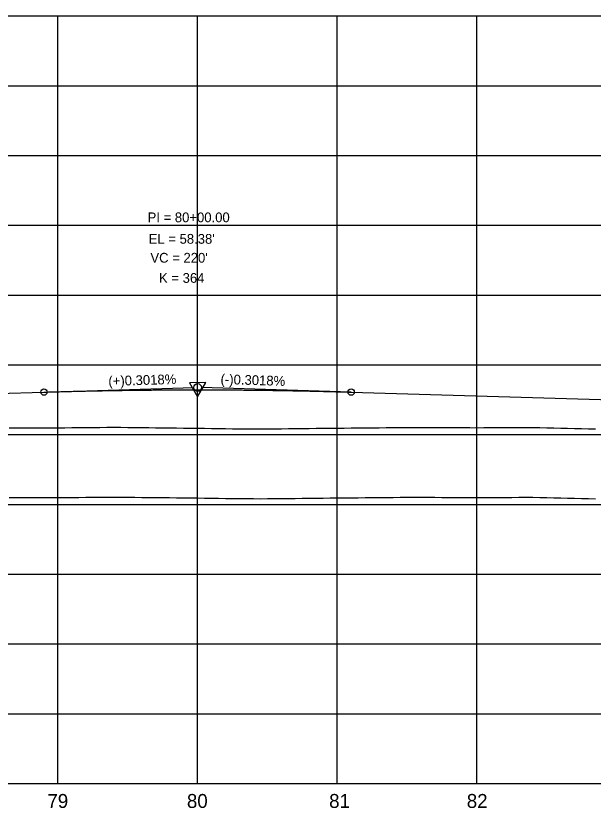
# Model space of a CAD drawing. Extents: x 2345490 to 2436403, y 465165 to 573888.
# Drawn here: x 2388191 to 2388605, y 557766 to 558334 of the extents above; entities that cross this region are included whole.
import ezdxf

# ---------------------------------------------------------------- set-up
doc = ezdxf.new("R2010")
doc.units = 0
for name, color, linetype in [('Old_Level_1', 7, 'Continuous'), ('Old_Level_2', 7, 'Continuous'), ('Old_Level_57', 7, 'Continuous'), ('Old_Level_62', 7, 'Continuous'), ('Old_Level_63', 7, 'Continuous')]:
    doc.layers.add(name, color=color, linetype=linetype)

msp = doc.modelspace()

# ---------------------------------------------------------------- linework, layer by layer
at = {"layer": 'Old_Level_1'}
for points in [[(2388186.5425, 557989.0075), (2388191.5425, 557989.001), (2388196.5425, 557988.999), (2388201.5425, 557988.99675), (2388206.5425, 557988.99475), (2388211.5425, 557988.99275), (2388216.5425, 557988.991), (2388221.5425, 557989.03825), (2388226.5425, 557989.08975), (2388231.5425, 557989.1415), (2388236.5425, 557989.193), (2388241.5425, 557989.24475), (2388246.5425, 557989.29625), (2388251.5425, 557989.348), (2388256.5425, 557989.39975), (2388261.5425, 557989.417), (2388266.5425, 557989.3615), (2388271.5425, 557989.3055), (2388276.5425, 557989.2495), (2388281.5425, 557989.19325), (2388286.5425, 557989.13675), (2388291.5425, 557989.08), (2388296.5425, 557989.02325), (2388301.5425, 557988.96625), (2388306.5425, 557988.909), (2388311.5425, 557988.8515), (2388316.5425, 557988.794), (2388321.5425, 557988.73625)], [(2388321.5425, 557988.73625), (2388326.5425, 557988.67825), (2388331.5425, 557988.61675), (2388336.5425, 557988.54025), (2388341.5425, 557988.46375), (2388346.5425, 557988.39275), (2388351.5425, 557988.35375), (2388356.5425, 557988.31475), (2388361.5425, 557988.2755), (2388366.5425, 557988.23625), (2388371.5425, 557988.269), (2388376.5425, 557988.32075), (2388381.5425, 557988.3725), (2388386.5425, 557988.4245), (2388391.5425, 557988.47675), (2388396.5425, 557988.529), (2388401.5425, 557988.5815), (2388406.5425, 557988.63275), (2388411.5425, 557988.681), (2388416.5425, 557988.72975), (2388421.5425, 557988.7785), (2388426.5425, 557988.82725), (2388431.5425, 557988.87625), (2388436.5425, 557988.9255), (2388441.5425, 557988.97475), (2388446.5425, 557989.02425), (2388451.5425, 557989.07375), (2388456.5425, 557989.1235), (2388461.5425, 557989.1735), (2388466.5425, 557989.2235), (2388471.5425, 557989.2405), (2388476.5425, 557989.2405), (2388481.5425, 557989.24775), (2388486.5425, 557989.23675), (2388491.5425, 557989.21575), (2388496.5425, 557989.195), (2388501.5425, 557989.17425), (2388506.5425, 557989.1535), (2388511.5425, 557989.133), (2388516.5425, 557989.1125), (2388521.5425, 557989.1), (2388526.5425, 557989.11675), (2388531.5425, 557989.1335), (2388536.5425, 557989.1505), (2388541.5425, 557989.1675), (2388546.5425, 557989.18475), (2388551.5425, 557989.20175), (2388556.5425, 557989.219), (2388561.5425, 557989.2365), (2388566.5425, 557989.16025), (2388571.5425, 557989.04), (2388576.5425, 557988.9195), (2388581.5425, 557988.7985), (2388586.5425, 557988.67725), (2388591.5425, 557988.5555), (2388596.5425, 557988.4335), (2388601.5425, 557988.31125), (2388606.5425, 557988.1885)]]:
    msp.add_lwpolyline(points, dxfattribs=at)
at = {"layer": 'Old_Level_2'}
for p, q in [((2387881.5425, 558054.63275), (2388211.5425, 558064.593)), ((2388211.5425, 558064.593), (2388318.794, 558067.83)), ((2388431.5425, 558064.593), (2388324.29125, 558067.83)), ((2388431.5425, 558064.593), (2388621.5425, 558058.85825))]:
    msp.add_line(p, q, dxfattribs=at)
msp.add_lwpolyline([(2388327.416, 558071.36575), (2388315.6735, 558071.35125), (2388321.557, 558061.233)], close=True, dxfattribs=at)
for centre, radius in [((2388321.5425, 558067.913), 2.75), ((2388211.5425, 558064.593), 2.25), ((2388431.5425, 558064.593), 2.25)]:
    msp.add_circle(centre, radius, dxfattribs=at)
msp.add_spline([(2388211.5425, 558064.593), (2388215.9425, 558064.723), (2388220.3425, 558064.84775), (2388224.7425, 558064.96725), (2388229.1425, 558065.0815), (2388233.5425, 558065.1905), (2388237.9425, 558065.294), (2388242.3425, 558065.39225), (2388246.7425, 558065.48525), (2388251.1425, 558065.573), (2388255.5425, 558065.65525), (2388259.9425, 558065.73225), (2388264.3425, 558065.804), (2388268.7425, 558065.8705), (2388273.1425, 558065.9315), (2388277.5425, 558065.98725), (2388281.9425, 558066.03775), (2388286.3425, 558066.083), (2388290.7425, 558066.12275), (2388295.1425, 558066.15725), (2388299.5425, 558066.1865), (2388303.9425, 558066.2105), (2388308.3425, 558066.229), (2388312.7425, 558066.24225), (2388317.1425, 558066.25025), (2388321.5425, 558066.253), (2388325.9425, 558066.25025), (2388330.3425, 558066.24225), (2388334.7425, 558066.229), (2388339.1425, 558066.2105), (2388343.5425, 558066.1865), (2388347.9425, 558066.15725), (2388352.3425, 558066.12275), (2388356.7425, 558066.083), (2388361.1425, 558066.03775), (2388365.5425, 558065.98725), (2388369.9425, 558065.9315), (2388374.3425, 558065.8705), (2388378.7425, 558065.804), (2388383.1425, 558065.73225), (2388387.5425, 558065.65525), (2388391.9425, 558065.573), (2388396.3425, 558065.48525), (2388400.7425, 558065.39225), (2388405.1425, 558065.294), (2388409.5425, 558065.1905), (2388413.9425, 558065.0815), (2388418.3425, 558064.96725), (2388422.7425, 558064.84775), (2388427.1425, 558064.723), (2388431.5425, 558064.593)], degree=3, dxfattribs=at)
at = {"layer": 'Old_Level_57'}
for p, q in [((2381271.54275, 558334.11325), (2393041.55275, 558334.11325)), ((2388221.54225, 557784.21325), (2388221.54225, 558334.21325)), ((2388221.54225, 557784.11325), (2388221.54225, 558334.11325)), ((2388321.54225, 557784.21325), (2388321.54225, 558334.21325)), ((2388321.54225, 557784.11325), (2388321.54225, 558334.11325)), ((2388421.54225, 557784.21325), (2388421.54225, 558334.21325)), ((2388421.54225, 557784.11325), (2388421.54225, 558334.11325)), ((2388521.54225, 557784.21325), (2388521.54225, 558334.21325)), ((2388521.54225, 557784.11325), (2388521.54225, 558334.11325)), ((2381271.54275, 558284.11325), (2393041.55275, 558284.11325)), ((2381271.54275, 558234.11325), (2393041.55275, 558234.11325)), ((2381271.54275, 558184.11325), (2393041.55275, 558184.11325)), ((2381271.54275, 558134.11325), (2393041.55275, 558134.11325)), ((2381271.54275, 558084.11325), (2393041.55275, 558084.11325)), ((2381271.5425, 558034.11325), (2393041.55275, 558034.11325)), ((2381271.54275, 557984.11325), (2393041.55275, 557984.11325)), ((2381271.5425, 557934.11325), (2393041.55275, 557934.11325)), ((2381271.54275, 557884.11325), (2393041.55275, 557884.11325)), ((2381271.5425, 557834.11325), (2393041.55275, 557834.11325)), ((2381271.54275, 557784.11325), (2393041.55275, 557784.11325))]:
    msp.add_line(p, q, dxfattribs=at)
at = {"layer": 'Old_Level_62'}
for points in [[(2388186.5425, 558039.0135), (2388191.5425, 558039.007), (2388196.5425, 558039.005), (2388201.5425, 558039.00275), (2388206.5425, 558039.00075), (2388211.5425, 558038.99875), (2388216.5425, 558038.997), (2388221.5425, 558039.04425), (2388226.5425, 558039.09575), (2388231.5425, 558039.1475), (2388236.5425, 558039.199), (2388241.5425, 558039.25075), (2388246.5425, 558039.30225), (2388251.5425, 558039.354), (2388256.5425, 558039.40575), (2388261.5425, 558039.423), (2388266.5425, 558039.3675), (2388271.5425, 558039.3115), (2388276.5425, 558039.2555), (2388281.5425, 558039.19925), (2388286.5425, 558039.14275), (2388291.5425, 558039.086), (2388296.5425, 558039.02925), (2388301.5425, 558038.97225), (2388306.5425, 558038.915), (2388311.5425, 558038.8575), (2388316.5425, 558038.8), (2388321.5425, 558038.74225)], [(2388321.5425, 558038.74225), (2388326.5425, 558038.68425), (2388331.5425, 558038.62275), (2388336.5425, 558038.54625), (2388341.5425, 558038.46975), (2388346.5425, 558038.39875), (2388351.5425, 558038.35975), (2388356.5425, 558038.32075), (2388361.5425, 558038.2815), (2388366.5425, 558038.24225), (2388371.5425, 558038.275), (2388376.5425, 558038.32675), (2388381.5425, 558038.3785), (2388386.5425, 558038.4305), (2388391.5425, 558038.48275), (2388396.5425, 558038.535), (2388401.5425, 558038.5875), (2388406.5425, 558038.63875), (2388411.5425, 558038.687), (2388416.5425, 558038.73575), (2388421.5425, 558038.7845), (2388426.5425, 558038.83325), (2388431.5425, 558038.88225), (2388436.5425, 558038.9315), (2388441.5425, 558038.98075), (2388446.5425, 558039.03025), (2388451.5425, 558039.07975), (2388456.5425, 558039.1295), (2388461.5425, 558039.1795), (2388466.5425, 558039.2295), (2388471.5425, 558039.2465), (2388476.5425, 558039.2465), (2388481.5425, 558039.25375), (2388486.5425, 558039.24275), (2388491.5425, 558039.22175), (2388496.5425, 558039.201), (2388501.5425, 558039.18025), (2388506.5425, 558039.1595), (2388511.5425, 558039.139), (2388516.5425, 558039.1185), (2388521.5425, 558039.106), (2388526.5425, 558039.12275), (2388531.5425, 558039.1395), (2388536.5425, 558039.1565), (2388541.5425, 558039.1735), (2388546.5425, 558039.19075), (2388551.5425, 558039.20775), (2388556.5425, 558039.225), (2388561.5425, 558039.2425), (2388566.5425, 558039.16625), (2388571.5425, 558039.046), (2388576.5425, 558038.9255), (2388581.5425, 558038.8045), (2388586.5425, 558038.68325), (2388591.5425, 558038.5615), (2388596.5425, 558038.4395), (2388601.5425, 558038.31725), (2388606.5425, 558038.1945)]]:
    msp.add_lwpolyline(points, dxfattribs=at)
at = {"layer": 'Old_Level_63'}
msp.add_line((2381321.5425, 557784.113), (2393019.104, 557784.113), dxfattribs=at)

# ---------------------------------------------------------------- texts
at = {"layer": 'Old_Level_1'}
for s, p in [('79', (2388214.053, 557766.613)), ('80', (2388313.929, 557766.613)), ('81', (2388415.7685, 557766.613)), ('82', (2388514.31675, 557766.613))]:
    msp.add_text(s, height=10.000001, dxfattribs=at).set_placement(p)
at = {"layer": 'Old_Level_2'}
for s, height, p in [('PI = 80+00.00', 7.0000005, (2388285.75875, 558186.318)), ("EL = 58.38'", 7.0000005, (2388286.5425, 558170.913)), ("VC = 220'", 7.000001, (2388287.784, 558157.36375)), ('K = 364', 7.000001, (2388293.94575, 558142.90175))]:
    msp.add_text(s, height=height, dxfattribs=at).set_placement(p)
for s, rotation, p in [('(+)0.3018%', 1.7287667, (2388257.7845, 558068.98975)), ('(-)0.3018%', 358.2712333, (2388337.9295, 558070.41975))]:
    msp.add_text(s, height=7.000001, rotation=rotation, dxfattribs=at).set_placement(p)

doc.saveas('drawing.dxf')
